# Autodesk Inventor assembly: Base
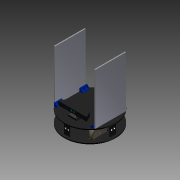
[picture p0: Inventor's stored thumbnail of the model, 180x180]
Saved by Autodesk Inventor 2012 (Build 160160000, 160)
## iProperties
Created: 2014-02
Part Number: Base
Document SubType Name: Assembly
Designer: Aser
Author: Aser
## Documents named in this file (11)
- D:\TechDev\Robotics\ROSADP\MockUp\MobileBase\Base.iam
- D:\TechDev\Robotics\ROSADP\MockUp\MobileBase\Mobile_Baes_Base.ipt
- D:\TechDev\Robotics\ROSADP\MockUp\MobileBase\SG775125000-40K.ipt
- D:\TechDev\Robotics\ROSADP\MockUp\MobileBase\Wheel.ipt
- D:\TechDev\Robotics\ROSADP\MockUp\MobileBase\Sealed Lead Acid Battery 12V - 12Ah.ipt
- D:\TechDev\Robotics\ROSADP\MockUp\MobileBase\Mobile_Baes_Top.ipt
- D:\TechDev\Robotics\ROSADP\Imported Components\UltraSonicSensor\UltraSonicSensor.iam
- D:\TechDev\Robotics\ROSADP\MockUp\MobileBase\Struts.ipt
- D:\TechDev\Robotics\ROSADP\Imported Components\kinect-sensor\kinect sensor.ipt
- D:\TechDev\Robotics\ROSADP\MockUp\MobileBase\Gusseted Angle Bracket.ipt
- D:\TechDev\Robotics\ROSADP\MockUp\Torso\OutterSides.ipt
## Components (22 placed, 10 different names)
1. Mobile_Baes_Base:1 — Angle:1, Mate:3, Flush:2, Flush:3, Mate:4, Mate:7, Mate:8, Mate:9, Mate:12, Mate:13, Mate:14, Mate:17, Mate:18, Mate:19, Mate:22, Mate:23, Mate:24, Mate:25, Mate:26, Mate:27
2. SG775125000-40K:1 — Mate:1, Mate:2, Flush:1, Angle:1, Mate:3, Flush:3, Mate:4, Flush:4
3. SG775125000-40K:2 — Mate:1, Mate:2, Flush:1, Flush:2, Mate:6, Flush:5, Mate:10, Mate:11
4. Wheel:1 — Mate:5, Flush:4
5. Wheel:2 — Mate:5, Mate:6, Flush:5
6. Sealed Lead Acid Battery 12V - 12Ah:1 — Mate:7, Angle:2, Mate:10, Mate:11
7. Mobile_Baes_Top:1 — Mate:8, Mate:9, Mate:32, Mate:33, Mate:34, Mate:35, Mate:36, Tangent:1, Tangent:2, Tangent:3, Tangent:4, Mate:39
8. UltraSonicSensor:1 [sub-assembly] — Angle:2, Flush:6, Flush:7, Flush:9, Flush:10, Mate:15, Mate:16, Mate:28
9. UltraSonicSensor:2 [sub-assembly] — Flush:6, Flush:8, Mate:31
10. UltraSonicSensor:3 [sub-assembly] — Flush:7, Flush:8, Mate:20, Mate:21, Mate:29
11. UltraSonicSensor:4 [sub-assembly] — Flush:9, Flush:10, Mate:30
12. Struts:1 — Mate:12, Mate:13, Mate:14, Mate:15, Mate:16, Mate:28
13. Struts:2 — Mate:17, Mate:18, Mate:19, Mate:20, Mate:21, Mate:29
14. Struts:3 — Mate:22, Mate:23, Mate:24, Mate:30, Flush:11, Flush:12
15. Struts:4 — Mate:25, Mate:26, Mate:27, Mate:31
16. kinect sensor:1 — Mate:32, Flush:11, Flush:12
17. Gusseted Angle Bracket:1 — Mate:34, Tangent:3, Flush:13, Flush:16
18. Gusseted Angle Bracket:2 — Mate:33, Tangent:1, Flush:14, Flush:15, Mate:37, Mate:38, Flush:17
19. Gusseted Angle Bracket:3 — Mate:35, Tangent:4, Flush:13, Flush:14, Mate:40
20. Gusseted Angle Bracket:4 — Mate:36, Tangent:2, Flush:15, Flush:16, Mate:37
21. OutterSides:1 — Mate:38, Mate:39, Flush:17, Flush:18, Flush:19
22. OutterSides:2 — Flush:18, Flush:19, Mate:40
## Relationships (65: Mate 40, Flush 19, Tangent 4, Angle 2)
- Mate:1: SG775125000-40K:1 ↔ SG775125000-40K:2
- Mate:2: SG775125000-40K:1 ↔ SG775125000-40K:2
- Flush:1: SG775125000-40K:1 ↔ SG775125000-40K:2
- Angle:1: Mobile_Baes_Base:1 ↔ SG775125000-40K:1
- Mate:3: Mobile_Baes_Base:1 ↔ SG775125000-40K:1
- Flush:2: Mobile_Baes_Base:1 ↔ SG775125000-40K:2
- Flush:3: Mobile_Baes_Base:1 ↔ SG775125000-40K:1
- Mate:4: Mobile_Baes_Base:1 ↔ SG775125000-40K:1
- Mate:5: Wheel:1 ↔ Wheel:2
- Mate:6: SG775125000-40K:2 ↔ Wheel:2
- Flush:4: SG775125000-40K:1 ↔ Wheel:1
- Flush:5: SG775125000-40K:2 ↔ Wheel:2
- Mate:7: Mobile_Baes_Base:1 ↔ Sealed Lead Acid Battery 12V - 12Ah:1
- Mate:8: Mobile_Baes_Base:1 ↔ Mobile_Baes_Top:1
- Mate:9: Mobile_Baes_Base:1 ↔ Mobile_Baes_Top:1
- Angle:2: Sealed Lead Acid Battery 12V - 12Ah:1 ↔ UltraSonicSensor:1
- Mate:10: SG775125000-40K:2 ↔ Sealed Lead Acid Battery 12V - 12Ah:1
- Mate:11: SG775125000-40K:2 ↔ Sealed Lead Acid Battery 12V - 12Ah:1
- Flush:6: UltraSonicSensor:1 ↔ UltraSonicSensor:2
- Flush:7: UltraSonicSensor:1 ↔ UltraSonicSensor:3
- Flush:8: UltraSonicSensor:2 ↔ UltraSonicSensor:3
- Flush:9: UltraSonicSensor:1 ↔ UltraSonicSensor:4
- Flush:10: UltraSonicSensor:1 ↔ UltraSonicSensor:4
- Mate:12: Mobile_Baes_Base:1 ↔ Struts:1
- Mate:13: Mobile_Baes_Base:1 ↔ Struts:1
- Mate:14: Mobile_Baes_Base:1 ↔ Struts:1
- Mate:15: UltraSonicSensor:1 ↔ Struts:1
- Mate:16: UltraSonicSensor:1 ↔ Struts:1
- Mate:17: Mobile_Baes_Base:1 ↔ Struts:2
- Mate:18: Mobile_Baes_Base:1 ↔ Struts:2
- Mate:19: Mobile_Baes_Base:1 ↔ Struts:2
- Mate:20: UltraSonicSensor:3 ↔ Struts:2
- Mate:21: UltraSonicSensor:3 ↔ Struts:2
- Mate:22: Mobile_Baes_Base:1 ↔ Struts:3
- Mate:23: Mobile_Baes_Base:1 ↔ Struts:3
- Mate:24: Mobile_Baes_Base:1 ↔ Struts:3
- Mate:25: Mobile_Baes_Base:1 ↔ Struts:4
- Mate:26: Mobile_Baes_Base:1 ↔ Struts:4
- Mate:27: Mobile_Baes_Base:1 ↔ Struts:4
- Mate:28: UltraSonicSensor:1 ↔ Struts:1
- Mate:29: UltraSonicSensor:3 ↔ Struts:2
- Mate:30: UltraSonicSensor:4 ↔ Struts:3
- Mate:31: UltraSonicSensor:2 ↔ Struts:4
- Mate:32: Mobile_Baes_Top:1 ↔ kinect sensor:1
- Flush:11: Struts:3 ↔ kinect sensor:1
- Flush:12: Struts:3 ↔ kinect sensor:1
- Mate:33: Mobile_Baes_Top:1 ↔ Gusseted Angle Bracket:2
- Mate:34: Mobile_Baes_Top:1 ↔ Gusseted Angle Bracket:1
- Mate:35: Mobile_Baes_Top:1 ↔ Gusseted Angle Bracket:3
- Mate:36: Mobile_Baes_Top:1 ↔ Gusseted Angle Bracket:4
- Tangent:1: Mobile_Baes_Top:1 ↔ Gusseted Angle Bracket:2
- Tangent:2: Mobile_Baes_Top:1 ↔ Gusseted Angle Bracket:4
- Tangent:3: Mobile_Baes_Top:1 ↔ Gusseted Angle Bracket:1
- Tangent:4: Mobile_Baes_Top:1 ↔ Gusseted Angle Bracket:3
- Flush:13: Gusseted Angle Bracket:1 ↔ Gusseted Angle Bracket:3
- Flush:14: Gusseted Angle Bracket:2 ↔ Gusseted Angle Bracket:3
- Flush:15: Gusseted Angle Bracket:2 ↔ Gusseted Angle Bracket:4
- Flush:16: Gusseted Angle Bracket:1 ↔ Gusseted Angle Bracket:4
- Mate:37: Gusseted Angle Bracket:2 ↔ Gusseted Angle Bracket:4
- Mate:38: Gusseted Angle Bracket:2 ↔ OutterSides:1
- Mate:39: Mobile_Baes_Top:1 ↔ OutterSides:1
- Flush:17: Gusseted Angle Bracket:2 ↔ OutterSides:1
- Flush:18: OutterSides:1 ↔ OutterSides:2
- Flush:19: OutterSides:1 ↔ OutterSides:2
- Mate:40: Gusseted Angle Bracket:3 ↔ OutterSides:2
